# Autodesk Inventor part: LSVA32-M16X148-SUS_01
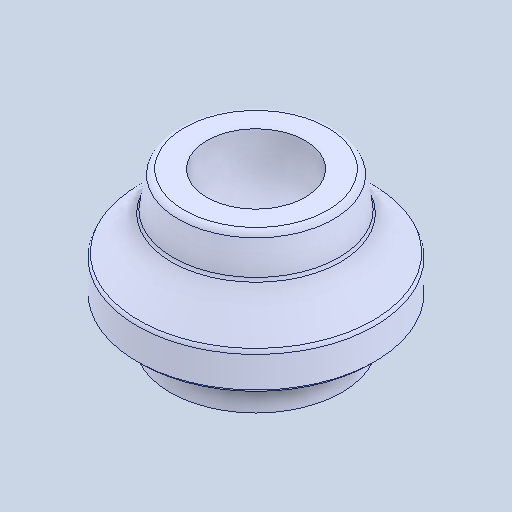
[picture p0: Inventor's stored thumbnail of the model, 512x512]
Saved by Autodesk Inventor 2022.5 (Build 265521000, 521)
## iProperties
Created: 2024-08
Part Number: LSVA32-M16X148-SUS_01
Material: 一般
Document SubType Name: Modeling
Designer: ImaoCorp
Density: 1 g/cm^3
Appearance: 既定
Author: ImaoCorp
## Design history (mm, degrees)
feature "LSVA32-M16X148-SUS_01"
node "ソリッド1"
